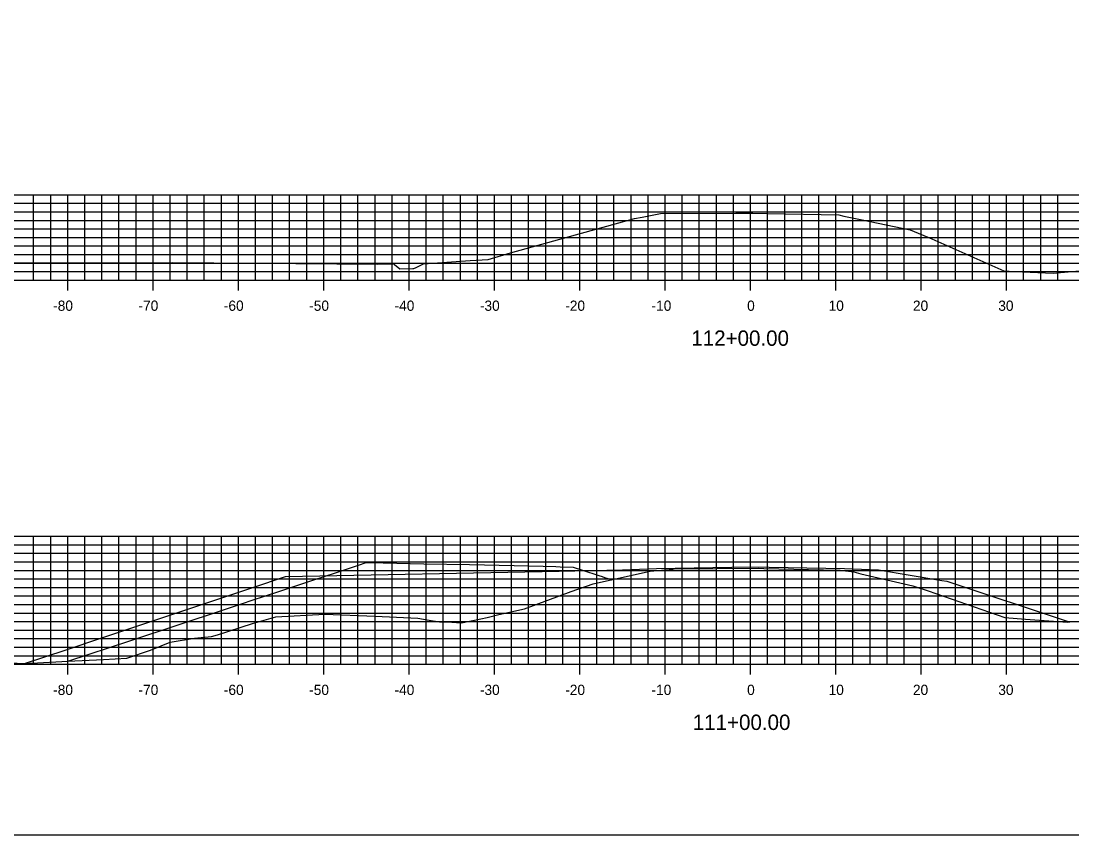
# Model space of a CAD drawing. Extents: x 1661012 to 1662122, y 670053 to 671852.
# Drawn here: x 1661506.5 to 1661629.7, y 671274.1 to 671369.5 of the extents above; entities that cross this region are included whole.
import ezdxf

# ---------------------------------------------------------------- set-up
doc = ezdxf.new("R2010")
doc.units = 0
for name, color, linetype in [('R_Concrete', 7, 'Continuous'), ('R_Concrete Hidden', 7, 'Continuous'), ('R_Erosion', 7, 'Continuous'), ('R_Exist Surface', 7, 'Continuous'), ('R_Proposed Road', 7, 'Continuous'), ('R_ROW Annot', 7, 'Continuous')]:
    doc.layers.add(name, color=color, linetype=linetype)

msp = doc.modelspace()

# ---------------------------------------------------------------- linework, layer by layer
at = {"layer": 'R_Concrete'}
for p, q in [((1661441.99, 671349.12), (1661741.99, 671349.12)), ((1661507.99, 671339.12), (1661507.99, 671349.12)), ((1661509.99, 671339.12), (1661509.99, 671349.12)), ((1661511.99, 671339.12), (1661511.99, 671349.12)), ((1661513.99, 671339.12), (1661513.99, 671349.12)), ((1661515.99, 671339.12), (1661515.99, 671349.12)), ((1661517.99, 671339.12), (1661517.99, 671349.12)), ((1661519.99, 671339.12), (1661519.99, 671349.12)), ((1661521.99, 671339.12), (1661521.99, 671349.12)), ((1661523.99, 671339.12), (1661523.99, 671349.12)), ((1661525.99, 671339.12), (1661525.99, 671349.12)), ((1661527.99, 671339.12), (1661527.99, 671349.12)), ((1661529.99, 671339.12), (1661529.99, 671349.12)), ((1661531.99, 671339.12), (1661531.99, 671349.12)), ((1661533.99, 671339.12), (1661533.99, 671349.12)), ((1661535.99, 671339.12), (1661535.99, 671349.12)), ((1661537.99, 671339.12), (1661537.99, 671349.12)), ((1661539.99, 671339.12), (1661539.99, 671349.12)), ((1661541.99, 671339.12), (1661541.99, 671349.12)), ((1661543.99, 671339.12), (1661543.99, 671349.12)), ((1661545.99, 671339.12), (1661545.99, 671349.12)), ((1661547.99, 671339.12), (1661547.99, 671349.12)), ((1661549.99, 671339.12), (1661549.99, 671349.12)), ((1661551.99, 671339.12), (1661551.99, 671349.12)), ((1661553.99, 671339.12), (1661553.99, 671349.12)), ((1661555.99, 671339.12), (1661555.99, 671349.12)), ((1661557.99, 671339.12), (1661557.99, 671349.12)), ((1661559.99, 671339.12), (1661559.99, 671349.12)), ((1661561.99, 671339.12), (1661561.99, 671349.12)), ((1661563.99, 671339.12), (1661563.99, 671349.12)), ((1661565.99, 671339.12), (1661565.99, 671349.12)), ((1661567.99, 671339.12), (1661567.99, 671349.12)), ((1661569.99, 671339.12), (1661569.99, 671349.12)), ((1661571.99, 671339.12), (1661571.99, 671349.12)), ((1661573.99, 671339.12), (1661573.99, 671349.12)), ((1661575.99, 671339.12), (1661575.99, 671349.12)), ((1661577.99, 671339.12), (1661577.99, 671349.12)), ((1661579.99, 671339.12), (1661579.99, 671349.12)), ((1661581.99, 671339.12), (1661581.99, 671349.12)), ((1661583.99, 671339.12), (1661583.99, 671349.12)), ((1661585.99, 671339.12), (1661585.99, 671349.12)), ((1661587.99, 671339.12), (1661587.99, 671349.12)), ((1661589.99, 671339.12), (1661589.99, 671349.12)), ((1661591.99, 671339.12), (1661591.99, 671349.12)), ((1661593.99, 671339.12), (1661593.99, 671349.12)), ((1661595.99, 671339.12), (1661595.99, 671349.12)), ((1661597.99, 671339.12), (1661597.99, 671349.12)), ((1661599.99, 671339.12), (1661599.99, 671349.12)), ((1661601.99, 671339.12), (1661601.99, 671349.12)), ((1661603.99, 671339.12), (1661603.99, 671349.12)), ((1661605.99, 671339.12), (1661605.99, 671349.12)), ((1661607.99, 671339.12), (1661607.99, 671349.12)), ((1661609.99, 671339.12), (1661609.99, 671349.12)), ((1661611.99, 671339.12), (1661611.99, 671349.12)), ((1661613.99, 671339.12), (1661613.99, 671349.12)), ((1661615.99, 671339.12), (1661615.99, 671349.12)), ((1661617.99, 671339.12), (1661617.99, 671349.12)), ((1661619.99, 671339.12), (1661619.99, 671349.12)), ((1661621.99, 671339.12), (1661621.99, 671349.12)), ((1661623.99, 671339.12), (1661623.99, 671349.12)), ((1661625.99, 671339.12), (1661625.99, 671349.12)), ((1661627.99, 671339.12), (1661627.99, 671349.12)), ((1661441.99, 671348.12), (1661741.99, 671348.12)), ((1661441.99, 671347.12), (1661741.99, 671347.12)), ((1661441.99, 671346.12), (1661741.99, 671346.12)), ((1661441.99, 671345.12), (1661741.99, 671345.12)), ((1661441.99, 671344.12), (1661741.99, 671344.12)), ((1661441.99, 671343.12), (1661741.99, 671343.12)), ((1661441.99, 671342.12), (1661741.99, 671342.12)), ((1661441.99, 671341.12), (1661741.99, 671341.12)), ((1661441.99, 671340.12), (1661741.99, 671340.12)), ((1661507.99, 671339.12), (1661507.99, 671339.72)), ((1661509.99, 671339.12), (1661509.99, 671339.72)), ((1661511.99, 671337.92), (1661511.99, 671340.32)), ((1661513.99, 671339.12), (1661513.99, 671339.72)), ((1661515.99, 671339.12), (1661515.99, 671339.72)), ((1661517.99, 671339.12), (1661517.99, 671339.72)), ((1661519.99, 671339.12), (1661519.99, 671339.72)), ((1661521.99, 671337.92), (1661521.99, 671340.32)), ((1661523.99, 671339.12), (1661523.99, 671339.72)), ((1661525.99, 671339.12), (1661525.99, 671339.72)), ((1661527.99, 671339.12), (1661527.99, 671339.72)), ((1661529.99, 671339.12), (1661529.99, 671339.72)), ((1661531.99, 671337.92), (1661531.99, 671340.32)), ((1661533.99, 671339.12), (1661533.99, 671339.72)), ((1661535.99, 671339.12), (1661535.99, 671339.72)), ((1661537.99, 671339.12), (1661537.99, 671339.72)), ((1661539.99, 671339.12), (1661539.99, 671339.72)), ((1661541.99, 671337.92), (1661541.99, 671340.32)), ((1661543.99, 671339.12), (1661543.99, 671339.72)), ((1661545.99, 671339.12), (1661545.99, 671339.72)), ((1661547.99, 671339.12), (1661547.99, 671339.72)), ((1661549.99, 671339.12), (1661549.99, 671339.72)), ((1661551.99, 671337.92), (1661551.99, 671340.32)), ((1661553.99, 671339.12), (1661553.99, 671339.72)), ((1661555.99, 671339.12), (1661555.99, 671339.72)), ((1661557.99, 671339.12), (1661557.99, 671339.72)), ((1661559.99, 671339.12), (1661559.99, 671339.72)), ((1661561.99, 671337.92), (1661561.99, 671340.32)), ((1661563.99, 671339.12), (1661563.99, 671339.72)), ((1661565.99, 671339.12), (1661565.99, 671339.72)), ((1661567.99, 671339.12), (1661567.99, 671339.72)), ((1661569.99, 671339.12), (1661569.99, 671339.72)), ((1661571.99, 671337.92), (1661571.99, 671340.32)), ((1661573.99, 671339.12), (1661573.99, 671339.72)), ((1661575.99, 671339.12), (1661575.99, 671339.72)), ((1661577.99, 671339.12), (1661577.99, 671339.72)), ((1661579.99, 671339.12), (1661579.99, 671339.72)), ((1661581.99, 671337.92), (1661581.99, 671340.32)), ((1661583.99, 671339.12), (1661583.99, 671339.72)), ((1661585.99, 671339.12), (1661585.99, 671339.72)), ((1661587.99, 671339.12), (1661587.99, 671339.72)), ((1661589.99, 671339.12), (1661589.99, 671339.72)), ((1661591.99, 671337.92), (1661591.99, 671340.32)), ((1661593.99, 671339.12), (1661593.99, 671339.72)), ((1661595.99, 671339.12), (1661595.99, 671339.72)), ((1661597.99, 671339.12), (1661597.99, 671339.72)), ((1661599.99, 671339.12), (1661599.99, 671339.72)), ((1661601.99, 671337.92), (1661601.99, 671340.32)), ((1661603.99, 671339.12), (1661603.99, 671339.72)), ((1661605.99, 671339.12), (1661605.99, 671339.72)), ((1661607.99, 671339.12), (1661607.99, 671339.72)), ((1661609.99, 671339.12), (1661609.99, 671339.72)), ((1661611.99, 671337.92), (1661611.99, 671340.32)), ((1661613.99, 671339.12), (1661613.99, 671339.72)), ((1661615.99, 671339.12), (1661615.99, 671339.72)), ((1661617.99, 671339.12), (1661617.99, 671339.72)), ((1661619.99, 671339.12), (1661619.99, 671339.72)), ((1661621.99, 671337.92), (1661621.99, 671340.32)), ((1661623.99, 671339.12), (1661623.99, 671339.72)), ((1661625.99, 671339.12), (1661625.99, 671339.72)), ((1661627.99, 671339.12), (1661627.99, 671339.72)), ((1661441.99, 671339.12), (1661741.99, 671339.12)), ((1661441.99, 671309.12), (1661741.99, 671309.12)), ((1661507.99, 671294.12), (1661507.99, 671309.12)), ((1661509.99, 671294.12), (1661509.99, 671309.12)), ((1661511.99, 671294.12), (1661511.99, 671309.12)), ((1661513.99, 671294.12), (1661513.99, 671309.12)), ((1661515.99, 671294.12), (1661515.99, 671309.12)), ((1661517.99, 671294.12), (1661517.99, 671309.12)), ((1661519.99, 671294.12), (1661519.99, 671309.12)), ((1661521.99, 671294.12), (1661521.99, 671309.12)), ((1661523.99, 671294.12), (1661523.99, 671309.12)), ((1661525.99, 671294.12), (1661525.99, 671309.12)), ((1661527.99, 671294.12), (1661527.99, 671309.12)), ((1661529.99, 671294.12), (1661529.99, 671309.12)), ((1661531.99, 671294.12), (1661531.99, 671309.12)), ((1661533.99, 671294.12), (1661533.99, 671309.12)), ((1661535.99, 671294.12), (1661535.99, 671309.12)), ((1661537.99, 671294.12), (1661537.99, 671309.12)), ((1661539.99, 671294.12), (1661539.99, 671309.12)), ((1661541.99, 671294.12), (1661541.99, 671309.12)), ((1661543.99, 671294.12), (1661543.99, 671309.12)), ((1661545.99, 671294.12), (1661545.99, 671309.12)), ((1661547.99, 671294.12), (1661547.99, 671309.12)), ((1661549.99, 671294.12), (1661549.99, 671309.12)), ((1661551.99, 671294.12), (1661551.99, 671309.12)), ((1661553.99, 671294.12), (1661553.99, 671309.12)), ((1661555.99, 671294.12), (1661555.99, 671309.12)), ((1661557.99, 671294.12), (1661557.99, 671309.12)), ((1661559.99, 671294.12), (1661559.99, 671309.12)), ((1661561.99, 671294.12), (1661561.99, 671309.12)), ((1661563.99, 671294.12), (1661563.99, 671309.12)), ((1661565.99, 671294.12), (1661565.99, 671309.12)), ((1661567.99, 671294.12), (1661567.99, 671309.12)), ((1661569.99, 671294.12), (1661569.99, 671309.12)), ((1661571.99, 671294.12), (1661571.99, 671309.12)), ((1661573.99, 671294.12), (1661573.99, 671309.12)), ((1661575.99, 671294.12), (1661575.99, 671309.12)), ((1661577.99, 671294.12), (1661577.99, 671309.12)), ((1661579.99, 671294.12), (1661579.99, 671309.12)), ((1661581.99, 671294.12), (1661581.99, 671309.12)), ((1661583.99, 671294.12), (1661583.99, 671309.12)), ((1661585.99, 671294.12), (1661585.99, 671309.12)), ((1661587.99, 671294.12), (1661587.99, 671309.12)), ((1661589.99, 671294.12), (1661589.99, 671309.12)), ((1661591.99, 671294.12), (1661591.99, 671309.12)), ((1661593.99, 671294.12), (1661593.99, 671309.12)), ((1661595.99, 671294.12), (1661595.99, 671309.12)), ((1661597.99, 671294.12), (1661597.99, 671309.12)), ((1661599.99, 671294.12), (1661599.99, 671309.12)), ((1661601.99, 671294.12), (1661601.99, 671309.12)), ((1661603.99, 671294.12), (1661603.99, 671309.12)), ((1661605.99, 671294.12), (1661605.99, 671309.12)), ((1661607.99, 671294.12), (1661607.99, 671309.12)), ((1661609.99, 671294.12), (1661609.99, 671309.12)), ((1661611.99, 671294.12), (1661611.99, 671309.12)), ((1661613.99, 671294.12), (1661613.99, 671309.12)), ((1661615.99, 671294.12), (1661615.99, 671309.12)), ((1661617.99, 671294.12), (1661617.99, 671309.12)), ((1661619.99, 671294.12), (1661619.99, 671309.12)), ((1661621.99, 671294.12), (1661621.99, 671309.12)), ((1661623.99, 671294.12), (1661623.99, 671309.12)), ((1661625.99, 671294.12), (1661625.99, 671309.12)), ((1661627.99, 671294.12), (1661627.99, 671309.12)), ((1661441.99, 671308.12), (1661741.99, 671308.12)), ((1661441.99, 671307.12), (1661741.99, 671307.12)), ((1661441.99, 671306.12), (1661741.99, 671306.12)), ((1661441.99, 671305.12), (1661741.99, 671305.12)), ((1661441.99, 671304.12), (1661741.99, 671304.12)), ((1661441.99, 671303.12), (1661741.99, 671303.12)), ((1661441.99, 671302.12), (1661741.99, 671302.12)), ((1661441.99, 671301.12), (1661741.99, 671301.12)), ((1661441.99, 671300.12), (1661741.99, 671300.12)), ((1661441.99, 671299.12), (1661741.99, 671299.12)), ((1661441.99, 671298.12), (1661741.99, 671298.12)), ((1661441.99, 671297.12), (1661741.99, 671297.12)), ((1661441.99, 671296.12), (1661741.99, 671296.12)), ((1661511.99, 671292.92), (1661511.99, 671295.32)), ((1661521.99, 671292.92), (1661521.99, 671295.32)), ((1661531.99, 671292.92), (1661531.99, 671295.32)), ((1661541.99, 671292.92), (1661541.99, 671295.32)), ((1661551.99, 671292.92), (1661551.99, 671295.32)), ((1661561.99, 671292.92), (1661561.99, 671295.32)), ((1661571.99, 671292.92), (1661571.99, 671295.32)), ((1661581.99, 671292.92), (1661581.99, 671295.32)), ((1661591.99, 671292.92), (1661591.99, 671295.32)), ((1661601.99, 671292.92), (1661601.99, 671295.32)), ((1661611.99, 671292.92), (1661611.99, 671295.32)), ((1661621.99, 671292.92), (1661621.99, 671295.32)), ((1661441.99, 671295.12), (1661741.99, 671295.12)), ((1661441.99, 671294.12), (1661741.99, 671294.12)), ((1661507.99, 671294.12), (1661507.99, 671294.72)), ((1661509.99, 671294.12), (1661509.99, 671294.72)), ((1661513.99, 671294.12), (1661513.99, 671294.72)), ((1661515.99, 671294.12), (1661515.99, 671294.72)), ((1661517.99, 671294.12), (1661517.99, 671294.72)), ((1661519.99, 671294.12), (1661519.99, 671294.72)), ((1661523.99, 671294.12), (1661523.99, 671294.72)), ((1661525.99, 671294.12), (1661525.99, 671294.72)), ((1661527.99, 671294.12), (1661527.99, 671294.72)), ((1661529.99, 671294.12), (1661529.99, 671294.72)), ((1661533.99, 671294.12), (1661533.99, 671294.72)), ((1661535.99, 671294.12), (1661535.99, 671294.72)), ((1661537.99, 671294.12), (1661537.99, 671294.72)), ((1661539.99, 671294.12), (1661539.99, 671294.72)), ((1661543.99, 671294.12), (1661543.99, 671294.72)), ((1661545.99, 671294.12), (1661545.99, 671294.72)), ((1661547.99, 671294.12), (1661547.99, 671294.72)), ((1661549.99, 671294.12), (1661549.99, 671294.72)), ((1661553.99, 671294.12), (1661553.99, 671294.72)), ((1661555.99, 671294.12), (1661555.99, 671294.72)), ((1661557.99, 671294.12), (1661557.99, 671294.72)), ((1661559.99, 671294.12), (1661559.99, 671294.72)), ((1661563.99, 671294.12), (1661563.99, 671294.72)), ((1661565.99, 671294.12), (1661565.99, 671294.72)), ((1661567.99, 671294.12), (1661567.99, 671294.72)), ((1661569.99, 671294.12), (1661569.99, 671294.72)), ((1661573.99, 671294.12), (1661573.99, 671294.72)), ((1661575.99, 671294.12), (1661575.99, 671294.72)), ((1661577.99, 671294.12), (1661577.99, 671294.72)), ((1661579.99, 671294.12), (1661579.99, 671294.72)), ((1661583.99, 671294.12), (1661583.99, 671294.72)), ((1661585.99, 671294.12), (1661585.99, 671294.72)), ((1661587.99, 671294.12), (1661587.99, 671294.72)), ((1661589.99, 671294.12), (1661589.99, 671294.72)), ((1661593.99, 671294.12), (1661593.99, 671294.72)), ((1661595.99, 671294.12), (1661595.99, 671294.72)), ((1661597.99, 671294.12), (1661597.99, 671294.72)), ((1661599.99, 671294.12), (1661599.99, 671294.72)), ((1661603.99, 671294.12), (1661603.99, 671294.72)), ((1661605.99, 671294.12), (1661605.99, 671294.72)), ((1661607.99, 671294.12), (1661607.99, 671294.72)), ((1661609.99, 671294.12), (1661609.99, 671294.72)), ((1661613.99, 671294.12), (1661613.99, 671294.72)), ((1661615.99, 671294.12), (1661615.99, 671294.72)), ((1661617.99, 671294.12), (1661617.99, 671294.72)), ((1661619.99, 671294.12), (1661619.99, 671294.72)), ((1661623.99, 671294.12), (1661623.99, 671294.72)), ((1661625.99, 671294.12), (1661625.99, 671294.72)), ((1661627.99, 671294.12), (1661627.99, 671294.72))]:
    msp.add_line(p, q, dxfattribs=at)
at = {"layer": 'R_Erosion'}
for points in [[(1661505.24, 671341.16), (1661524.29, 671341.18), (1661548.33, 671340.99), (1661549.93, 671341.01), (1661550.25, 671340.97), (1661550.28, 671340.94), (1661550.91, 671340.45), (1661552.41, 671340.49), (1661552.54, 671340.49), (1661552.8, 671340.61), (1661553.69, 671341.04), (1661559.15, 671341.41), (1661561.25, 671341.55), (1661563.88, 671342.32), (1661578.39, 671346.32), (1661579.29, 671346.5), (1661581.45, 671346.92), (1661590.27, 671346.95), (1661592.27, 671346.97), (1661594.02, 671346.94), (1661602.35, 671346.75), (1661602.93, 671346.62), (1661605.08, 671346.18), (1661609.74, 671345.2), (1661610.7, 671345), (1661613.23, 671343.94), (1661621.66, 671340.19), (1661622.97, 671340.13), (1661627.45, 671339.95), (1661638.01, 671340.88)], [(1661497.1, 671294.91), (1661506.58, 671294.21), (1661508.45, 671294.29), (1661512, 671294.48), (1661516.17, 671294.69), (1661518.92, 671294.85), (1661521.69, 671295.77), (1661523.97, 671296.71), (1661526.82, 671297.16), (1661528.82, 671297.36), (1661529.55, 671297.55), (1661533.62, 671298.89), (1661536.38, 671299.66), (1661542.12, 671299.97), (1661548.02, 671299.74), (1661553.01, 671299.51), (1661554.33, 671299.28), (1661555.55, 671299.1), (1661556.42, 671299.07), (1661558.11, 671298.98), (1661560.38, 671299.44), (1661561.12, 671299.58), (1661562.49, 671299.94), (1661565.52, 671300.61), (1661570.96, 671302.65), (1661573.54, 671303.54), (1661578.27, 671304.58), (1661580.22, 671305.04), (1661582.87, 671305.27), (1661582.98, 671305.28), (1661583.05, 671305.28), (1661592.88, 671305.36), (1661593.56, 671305.34), (1661602.28, 671305.14), (1661602.48, 671305.13), (1661604.1, 671304.96), (1661604.92, 671304.7), (1661611.02, 671303.32), (1661612.81, 671302.7), (1661621.77, 671299.58), (1661624.19, 671299.39), (1661628.57, 671299.1), (1661629.13, 671299.04), (1661629.66, 671299.12)]]:
    msp.add_lwpolyline(points, dxfattribs=at)
at = {"layer": 'R_Exist Surface'}
for p, q in [((1661441.99, 671339.12), (1661741.99, 671339.12)), ((1661441.99, 671294.12), (1661741.99, 671294.12))]:
    msp.add_line(p, q, dxfattribs=at)
at = {"layer": 'R_Proposed Road'}
msp.add_lwpolyline([(1661411.99, 671274.12), (1661771.99, 671274.12), (1661771.99, 671466.82), (1661411.99, 671466.82)], close=True, dxfattribs=at)
at = {"layer": 'R_ROW Annot'}
for points in [[(1661507.03, 671294.23), (1661511.68, 671295.78), (1661515.99, 671297.21), (1661533.69, 671303.11), (1661537.49, 671304.38), (1661569.58, 671305.03), (1661576.99, 671305.17), (1661580.99, 671305.33), (1661591.99, 671305.55), (1661602.99, 671305.33), (1661606.99, 671305.17), (1661614.4, 671303.94), (1661614.99, 671303.84), (1661629.32, 671299.07)], [(1661511.97, 671294.48), (1661512, 671294.49), (1661519.36, 671296.89), (1661530.34, 671300.53), (1661532.59, 671301.28), (1661533.47, 671301.58), (1661536.84, 671302.69), (1661537.66, 671302.96), (1661540.23, 671303.81), (1661542.49, 671304.56), (1661543.02, 671304.73), (1661546.06, 671305.73), (1661546.94, 671306.02), (1661548.32, 671306.02), (1661548.96, 671306.01), (1661553.7, 671305.9), (1661559.07, 671305.79), (1661564.3, 671305.67), (1661567.68, 671305.6), (1661569.19, 671305.57), (1661569.69, 671305.55), (1661571.22, 671305.49), (1661572.29, 671305.14), (1661574.22, 671304.51), (1661574.59, 671304.39), (1661574.89, 671304.29), (1661575.27, 671304.16), (1661575.71, 671304.02)]]:
    msp.add_lwpolyline(points, dxfattribs=at)

# ---------------------------------------------------------------- texts
at = {"layer": 'R_Concrete Hidden'}
for s, height, p in [('-80', 1.2, (1661510.28, 671335.52)), ('-70', 1.2, (1661520.28, 671335.52)), ('-60', 1.2, (1661530.28, 671335.52)), ('-50', 1.2, (1661540.28, 671335.52)), ('-40', 1.2, (1661550.28, 671335.52)), ('-30', 1.2, (1661560.28, 671335.52)), ('-20', 1.2, (1661570.28, 671335.52)), ('-10', 1.2, (1661580.39, 671335.52)), ('0', 1.2, (1661591.59, 671335.52)), ('10', 1.2, (1661601.14, 671335.52)), ('20', 1.2, (1661611.02, 671335.52)), ('30', 1.2, (1661621.02, 671335.52)), ('112+00.00', 1.8, (1661585.05, 671331.42)), ('-80', 1.2, (1661510.28, 671290.52)), ('-70', 1.2, (1661520.28, 671290.52)), ('-60', 1.2, (1661530.28, 671290.52)), ('-50', 1.2, (1661540.28, 671290.52)), ('-40', 1.2, (1661550.28, 671290.52)), ('-30', 1.2, (1661560.28, 671290.52)), ('-20', 1.2, (1661570.28, 671290.52)), ('-10', 1.2, (1661580.39, 671290.52)), ('0', 1.2, (1661591.59, 671290.52)), ('10', 1.2, (1661601.14, 671290.52)), ('20', 1.2, (1661611.02, 671290.52)), ('30', 1.2, (1661621.02, 671290.52)), ('111+00.00', 1.8, (1661585.22, 671286.42))]:
    msp.add_text(s, height=height, dxfattribs=at).set_placement(p)

doc.saveas('drawing.dxf')
